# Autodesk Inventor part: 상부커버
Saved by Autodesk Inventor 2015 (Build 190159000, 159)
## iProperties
Created: 2025-08
Part Number: 상부커버
Material: 일반
Document SubType Name: Modeling
Designer: USER
Density: 1 g/cm^3
Appearance: 기본값
Author: USER
Author: jhkim
Creation Date: 2025-08-05
Sending System: Autodesk Inventor 2026
Preprocessor: ST-DEVELOPER v20.1
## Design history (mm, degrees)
node "상부커버1"
node "솔리드1"
node "기준1"
